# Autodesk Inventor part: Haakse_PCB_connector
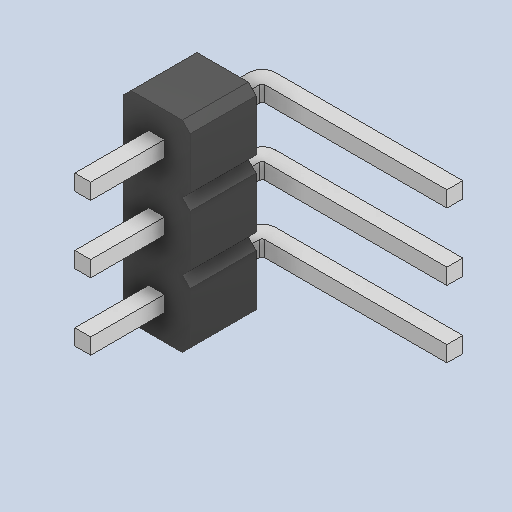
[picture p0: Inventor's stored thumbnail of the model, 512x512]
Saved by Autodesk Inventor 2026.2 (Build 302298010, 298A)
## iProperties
Created: 2023-02
Part Number: Haakse_PCB_connector
Material: Generic
Document SubType Name: Modeling
Designer: mel
Density: 1 g/cm^3
Appearance: Par défaut
Author: mel
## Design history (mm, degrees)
feature "Solid1"
node "Solide1"
